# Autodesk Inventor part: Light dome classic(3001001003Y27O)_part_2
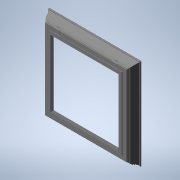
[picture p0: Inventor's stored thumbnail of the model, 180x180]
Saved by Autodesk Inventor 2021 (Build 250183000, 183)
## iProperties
Created: 2026-04
Part Number: Light dome classic(3001001003Y27O)_part_2
Material: Generic
Catalog Web Link: www.3dfindit.com
Description: Light dome classic_part_2-
Vendor: KINGSPAN
Document SubType Name: Modeling
Designer: psAdmin
Manufacturer: KINGSPAN
Mass: 9238.09 g
Surface Area: 18420.5 cm^2
Volume: 9238.09 cm^3
Density: 1 g/cm^3
Appearance: PSOLRGB-255-255-255
Category: PARTsolutions
Company: KINGSPAN
Title: Light dome classic(3001001003Y27O)_part_2
Author: Cadenas PARTsolutions
PSOL_IDENT_0: {$CADENAS_DATA/23d-libs/kingspan_kla/light_dome_classic/parts/part_2.prj},269 {VTYP=3D},{NB=Light do
PSOL_IDENT_1: me classic(3001001003Y27O)_part_2},{LINA=Light dome classic(3001001003Y27O)_part_2},{NN=Light dome c
PSOL_IDENT_2: lassic_part_2},{DATE=20.03.2025 09:30:52},{GEOMDATE=04.07.2024 05:51:00},{VERSION=},{LINEID=10},{WBV
PSOL_IDENT_3: AR=LODLEVEL,L,W,BA,SF,DP,OP,OC},{WBNUMERIC=W}  {NB=Light dome classic(3001001003Y27O)_part_2},{LINA=
PSOL_IDENT_4: Light dome classic(3001001003Y27O)_part_2},{KT=DUMMY},{IDNR=},{PN=Light dome classic},{LODLEVEL=300}
PSOL_IDENT_5: ,{L=100},{W=100},{WX=100,150,200,250,300},{LX=1000},{XWX=1000},{BA=3},{SF=Y},{SFX='Y','Yes','N','No'
PSOL_IDENT_6: },{DRIVE=1},{DPX='1', 'Natural ventilation', '2' , 'NSHEV (natural smoke, heat exhaust ventilation)'
PSOL_IDENT_7: , '3', 'Fixed','4','NSHE'},{DP=2},{OPX='7','24/48 V OPEN/CLOSE including ventilation function'},{OP=
PSOL_IDENT_8: 7},{OCX='O', 'Open', 'C', 'Closed'},{OC=O},{BAXX=56.97},{BAX='3', 'AK50 PVC', '2', 'AK30 PVC' , '7'
PSOL_IDENT_9: , 'AK30 AL/ST', '8', 'AK40 AL/ST', '9'  , 'AK50 AL/ST', '13' , 'AK30 AL/AL', '14' , 'AK40 AL/AL', '
PSOL_IDENT_10: 15' , 'AK50 AL/AL', '16' , 'AK50 ST-TG', '10', 'AK30 ST', '11'  , 'AK40 ST', '12', 'AK50 ST'}
NB: Light dome classic(3001001003Y27O)_part_2
NN: Light dome classic_part_2
NBSYN: $PN.($LODLEVEL.$L.$W.$BA.$SF.$DP.$OP.$OC.)_part_2
LINA: Light dome classic(3001001003Y27O)_part_2
CATALOG: Light + Air
PN: Light dome classic
LODLEVEL: 300
L: 100
W: 100
BA: AK50 PVC
SF: Yes
DP: NSHEV (natural smoke, heat exhaust ventilation)
OP: 24/48 V OPEN/CLOSE including ventilation function
OC: Open
SUPPLIER: KINGSPAN
ARTICLENO: Light dome classic(3001001003Y27O)_part_2
BOMINFO: Light dome classic(3001001003Y27O)_part_2
CREATOR: CADENAS GmbH
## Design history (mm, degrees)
sketch "Sketch_1"
  geometry: L1 (-393, 332)-(-395.2, 332); L2 (-395.2, 332)-(-395.2, 327); L3 (-395.2, 327)-(-424, 327); L4 (-424, 327)-(-424, 316); L5 (-424, 316)-(-467.8, 316); L6 (-472, 311.8)-(-472, 306.773); L7 (-477, 298.113)-(-489.32, 291); L8 (-489.32, 291)-(-500.849, 274.535); L9 (-500.849, 274.535)-(-496.754, 271.668); L10 (-496.754, 271.668)-(-508.226, 255.284); L11 (-508.226, 255.284)-(-504.129, 252.415); L12 (-504.129, 252.415)-(-515.6, 236.032); L13 (-515.6, 236.032)-(-511.507, 233.166); L14 (-511.507, 233.166)-(-521.208, 219.311); L15 (-521.208, 219.311)-(-532.773, 219.311); L16 (-532.773, 219.311)-(-532.773, 204.131); L17 (-532.773, 204.131)-(-525.173, 204.131); L18 (-519.959, 217.26)-(-508.443, 233.706); L19 (-508.443, 233.706)-(-512.536, 236.572); L20 (-512.536, 236.572)-(-501.065, 252.955); L21 (-501.065, 252.955)-(-505.162, 255.824); L22 (-505.162, 255.824)-(-493.69, 272.208); L23 (-493.69, 272.208)-(-497.785, 275.075); L24 (-497.785, 275.075)-(-487.798, 289.339); L25 (-487.798, 289.339)-(-481.456, 293); L26 (-481.456, 293)-(-393, 293); L27 (-393, 293)-(-393, 332); A1 r 4.2 centre (-467.8, 311.8) between (-467.8, 316) and (-472, 311.8); A2 r 10 centre (-482, 306.773) between (-477, 298.113) and (-472, 306.773); A3 r 7.6 centre (-525.173, 211.731) between (-525.173, 204.131) and (-519.959, 217.26)
  constraints: 54 end point, 6 point on circle, 3 centre point
extrude "Extrusion1" join sketch "Sketch_1" stored distance "d0" = 2000; taper "d1" = 0 deg
sketch "Sketch_2"
  geometry: L1 (388.2, 332)-(386, 332); L2 (386, 332)-(386, 293); L3 (386, 293)-(474.456, 293); L4 (474.456, 293)-(480.798, 289.339); L5 (480.798, 289.339)-(490.785, 275.075); L6 (490.785, 275.075)-(486.69, 272.208); L7 (486.69, 272.208)-(498.162, 255.824); L8 (498.162, 255.824)-(494.065, 252.955); L9 (494.065, 252.955)-(505.536, 236.572); L10 (505.536, 236.572)-(501.443, 233.706); L11 (501.443, 233.706)-(512.959, 217.26); L12 (518.173, 204.131)-(525.77, 204.131); L13 (525.77, 204.131)-(525.77, 219.311); L14 (525.77, 219.311)-(514.208, 219.311); L15 (514.208, 219.311)-(504.507, 233.166); L16 (504.507, 233.166)-(508.6, 236.032); L17 (508.6, 236.032)-(497.129, 252.415); L18 (497.129, 252.415)-(501.226, 255.284); L19 (501.226, 255.284)-(489.754, 271.668); L20 (489.754, 271.668)-(493.849, 274.535); L21 (493.849, 274.535)-(482.32, 291); L22 (482.32, 291)-(470, 298.113); L23 (465, 306.773)-(465, 311.8); L24 (460.8, 316)-(417, 316); L25 (417, 316)-(417, 327); L26 (417, 327)-(388.2, 327); L27 (388.2, 327)-(388.2, 332); A1 r 7.6 centre (518.173, 211.731) between (512.959, 217.26) and (518.173, 204.131); A2 r 10 centre (475, 306.773) between (465, 306.773) and (470, 298.113); A3 r 4.2 centre (460.8, 311.8) between (465, 311.8) and (460.8, 316)
  constraints: 54 end point, 6 point on circle, 3 centre point
extrude "Extrusion2" join sketch "Sketch_2" stored distance "d2" = 2000; taper "d3" = 0 deg
sketch "Sketch_3"
  geometry: L1 (534.773, 204.131)-(534.773, 219.311); L2 (534.773, 219.311)-(521.208, 219.311); L3 (521.208, 219.311)-(511.507, 233.166); L4 (511.507, 233.166)-(515.6, 236.032); L5 (515.6, 236.032)-(504.129, 252.415); L6 (504.129, 252.415)-(508.226, 255.284); L7 (508.226, 255.284)-(496.754, 271.668); L8 (496.754, 271.668)-(500.849, 274.535); L9 (500.849, 274.535)-(489.32, 291); L10 (489.32, 291)-(477, 298.113); L11 (472, 306.773)-(472, 311.8); L12 (467.8, 316)-(424, 316); L13 (424, 316)-(424, 327); L14 (424, 327)-(395.2, 327); L15 (395.2, 327)-(395.2, 332); L16 (395.2, 332)-(393, 332); L17 (393, 332)-(393, 293); L18 (393, 293)-(481.456, 293); L19 (481.456, 293)-(487.798, 289.339); L20 (487.798, 289.339)-(497.785, 275.075); L21 (497.785, 275.075)-(493.69, 272.208); L22 (493.69, 272.208)-(505.162, 255.824); L23 (505.162, 255.824)-(501.065, 252.955); L24 (501.065, 252.955)-(512.536, 236.572); L25 (512.536, 236.572)-(508.443, 233.706); L26 (508.443, 233.706)-(519.959, 217.26); L27 (525.173, 204.131)-(534.773, 204.131); A1 r 10 centre (482, 306.773) between (472, 306.773) and (477, 298.113); A2 r 4.2 centre (467.8, 311.8) between (472, 311.8) and (467.8, 316); A3 r 7.6 centre (525.173, 211.731) between (519.959, 217.26) and (525.173, 204.131)
  constraints: 54 end point, 6 point on circle, 3 centre point
extrude "Extrusion3" join sketch "Sketch_3" stored distance "d4" = 2000; taper "d5" = 0 deg
sketch "Sketch_4"
  geometry: L1 (-388.2, 332)-(-388.2, 327); L2 (-388.2, 327)-(-417, 327); L3 (-417, 327)-(-417, 316); L4 (-417, 316)-(-460.8, 316); L5 (-465, 311.8)-(-465, 306.773); L6 (-470, 298.113)-(-482.32, 291); L7 (-482.32, 291)-(-493.849, 274.535); L8 (-493.849, 274.535)-(-489.754, 271.668); L9 (-489.754, 271.668)-(-501.226, 255.284); L10 (-501.226, 255.284)-(-497.129, 252.415); L11 (-497.129, 252.415)-(-508.6, 236.032); L12 (-508.6, 236.032)-(-504.507, 233.166); L13 (-504.507, 233.166)-(-514.208, 219.311); L14 (-514.208, 219.311)-(-525.77, 219.311); L15 (-525.77, 219.311)-(-525.77, 204.131); L16 (-525.77, 204.131)-(-518.173, 204.131); L17 (-512.959, 217.26)-(-501.443, 233.706); L18 (-501.443, 233.706)-(-505.536, 236.572); L19 (-505.536, 236.572)-(-494.065, 252.955); L20 (-494.065, 252.955)-(-498.162, 255.824); L21 (-498.162, 255.824)-(-486.69, 272.208); L22 (-486.69, 272.208)-(-490.785, 275.075); L23 (-490.785, 275.075)-(-480.798, 289.339); L24 (-480.798, 289.339)-(-474.456, 293); L25 (-474.456, 293)-(-386, 293); L26 (-386, 293)-(-386, 332); L27 (-386, 332)-(-388.2, 332); A1 r 4.2 centre (-460.8, 311.8) between (-460.8, 316) and (-465, 311.8); A2 r 10 centre (-475, 306.773) between (-470, 298.113) and (-465, 306.773); A3 r 7.6 centre (-518.173, 211.731) between (-518.173, 204.131) and (-512.959, 217.26)
  constraints: 54 end point, 6 point on circle, 3 centre point
extrude "Extrusion4" join sketch "Sketch_4" stored distance "d6" = 2000; taper "d7" = 0 deg
sketch "Sketch_5"
  geometry: L1 (-393, 357)-(-1093, 357); L2 (-1093, 357)-(-1093, 80.939); L3 (-1093, 80.939)-(-527.437, 180.866); L4 (-527.437, 180.866)-(-532.657, 210.409); L5 (-525.724, 219.311)-(-521.208, 219.311); L6 (-521.208, 219.311)-(-511.507, 233.166); L7 (-511.507, 233.166)-(-515.6, 236.032); L8 (-515.6, 236.032)-(-504.129, 252.415); L9 (-504.129, 252.415)-(-508.226, 255.284); L10 (-508.226, 255.284)-(-496.754, 271.668); L11 (-496.754, 271.668)-(-500.849, 274.535); L12 (-500.849, 274.535)-(-489.32, 291); L13 (-489.32, 291)-(-477, 298.113); L14 (-472, 306.773)-(-472, 311.8); L15 (-467.8, 316)-(-424, 316); L16 (-424, 316)-(-424, 327); L17 (-424, 327)-(-395.2, 327); L18 (-395.2, 327)-(-395.2, 334); L19 (-395.2, 334)-(-393, 334); L20 (-393, 334)-(-393, 357); A1 r 7.6 centre (-525.173, 211.731) between (-525.724, 219.311) and (-532.657, 210.409); A2 r 10 centre (-482, 306.773) between (-477, 298.113) and (-472, 306.773); A3 r 4.2 centre (-467.8, 311.8) between (-467.8, 316) and (-472, 311.8)
  constraints: 40 end point, 6 point on circle, 3 centre point
extrude "Extrusion5" cut sketch "Sketch_5" stored distance "d8" = 2000; taper "d9" = 0 deg
sketch "Sketch_6"
  geometry: L1 (1093, 80.939)-(1093, 357); L2 (1093, 357)-(393, 357); L3 (393, 357)-(393, 334); L4 (393, 334)-(395.2, 334); L5 (395.2, 334)-(395.2, 327); L6 (395.2, 327)-(424, 327); L7 (424, 327)-(424, 316); L8 (424, 316)-(467.8, 316); L9 (472, 311.8)-(472, 306.773); L10 (477, 298.113)-(489.32, 291); L11 (489.32, 291)-(500.849, 274.535); L12 (500.849, 274.535)-(496.754, 271.668); L13 (496.754, 271.668)-(508.226, 255.284); L14 (508.226, 255.284)-(504.129, 252.415); L15 (504.129, 252.415)-(515.6, 236.032); L16 (515.6, 236.032)-(511.507, 233.166); L17 (511.507, 233.166)-(521.208, 219.311); L18 (521.208, 219.311)-(525.724, 219.311); L19 (532.657, 210.409)-(527.437, 180.866); L20 (527.437, 180.866)-(1093, 80.939); A1 r 4.2 centre (467.8, 311.8) between (472, 311.8) and (467.8, 316); A2 r 10 centre (482, 306.773) between (472, 306.773) and (477, 298.113); A3 r 7.6 centre (525.173, 211.731) between (532.657, 210.409) and (525.724, 219.311)
  constraints: 40 end point, 6 point on circle, 3 centre point
extrude "Extrusion6" cut sketch "Sketch_6" stored distance "d10" = 2000; taper "d11" = 0 deg
sketch "Sketch_7"
  geometry: L1 (1086, 357)-(386, 357); L2 (386, 357)-(386, 334); L3 (386, 334)-(388.2, 334); L4 (388.2, 334)-(388.2, 327); L5 (388.2, 327)-(417, 327); L6 (417, 327)-(417, 316); L7 (417, 316)-(460.8, 316); L8 (465, 311.8)-(465, 306.773); L9 (470, 298.113)-(482.32, 291); L10 (482.32, 291)-(493.849, 274.535); L11 (493.849, 274.535)-(489.754, 271.668); L12 (489.754, 271.668)-(501.226, 255.284); L13 (501.226, 255.284)-(497.129, 252.415); L14 (497.129, 252.415)-(508.6, 236.032); L15 (508.6, 236.032)-(504.507, 233.166); L16 (504.507, 233.166)-(514.208, 219.311); L17 (514.208, 219.311)-(518.724, 219.311); L18 (525.657, 210.409)-(516.957, 161.171); L19 (516.957, 161.171)-(1086, 60.629); L20 (1086, 60.629)-(1086, 357); A1 r 4.2 centre (460.8, 311.8) between (465, 311.8) and (460.8, 316); A2 r 10 centre (475, 306.773) between (465, 306.773) and (470, 298.113); A3 r 7.6 centre (518.173, 211.731) between (525.657, 210.409) and (518.724, 219.311)
  constraints: 40 end point, 6 point on circle, 3 centre point
extrude "Extrusion7" cut sketch "Sketch_7" stored distance "d12" = 2000; taper "d13" = 0 deg
sketch "Sketch_8"
  geometry: L1 (-1086, 357)-(-1086, 60.629); L2 (-1086, 60.629)-(-516.957, 161.171); L3 (-516.957, 161.171)-(-525.657, 210.409); L4 (-518.724, 219.311)-(-514.208, 219.311); L5 (-514.208, 219.311)-(-504.507, 233.166); L6 (-504.507, 233.166)-(-508.6, 236.032); L7 (-508.6, 236.032)-(-497.129, 252.415); L8 (-497.129, 252.415)-(-501.226, 255.284); L9 (-501.226, 255.284)-(-489.754, 271.668); L10 (-489.754, 271.668)-(-493.849, 274.535); L11 (-493.849, 274.535)-(-482.32, 291); L12 (-482.32, 291)-(-470, 298.113); L13 (-465, 306.773)-(-465, 311.8); L14 (-460.8, 316)-(-417, 316); L15 (-417, 316)-(-417, 327); L16 (-417, 327)-(-388.2, 327); L17 (-388.2, 327)-(-388.2, 334); L18 (-388.2, 334)-(-386, 334); L19 (-386, 334)-(-386, 357); L20 (-386, 357)-(-1086, 357); A1 r 7.6 centre (-518.173, 211.731) between (-518.724, 219.311) and (-525.657, 210.409); A2 r 10 centre (-475, 306.773) between (-470, 298.113) and (-465, 306.773); A3 r 4.2 centre (-460.8, 311.8) between (-460.8, 316) and (-465, 311.8)
  constraints: 40 end point, 6 point on circle, 3 centre point
extrude "Extrusion8" cut sketch "Sketch_8" stored distance "d14" = 2000; taper "d15" = 0 deg
sketch "Sketch_13"
  geometry: L1 (-319.461, 417.103)-(-318, 417); L2 (-318, 417)-(-316, 417); L3 (-316, 417)-(-316, 464.531); L4 (-316, 464.531)-(-303.205, 474.473); L5 (-308.009, 473.974)-(-307.436, 475.954); L6 (-304.441, 476.046)-(-318, 465.51); L7 (-318, 465.51)-(-318, 421); L8 (-318, 421)-(-319.461, 417.103); A1 r 4.5 centre (-306, 478) between (-303.205, 474.473) and (-308.009, 473.974); A2 r 2.5 centre (-306, 478) between (-304.441, 476.046) and (-307.436, 475.954)
  constraints: 16 end point, 4 point on circle, 2 centre point
extrude "Extrusion9" join sketch "Sketch_13" distance "d16" = 70; taper "d17" = 0 deg
sketch "Sketch_14"
  geometry: L1 (-319.461, 417.103)-(-318, 417); L2 (-318, 417)-(-316, 417); L3 (-316, 417)-(-316, 464.531); L4 (-316, 464.531)-(-303.205, 474.473); L5 (-308.009, 473.974)-(-307.436, 475.954); L6 (-304.441, 476.046)-(-318, 465.51); L7 (-318, 465.51)-(-318, 421); L8 (-318, 421)-(-319.461, 417.103); A1 r 4.5 centre (-306, 478) between (-303.205, 474.473) and (-308.009, 473.974); A2 r 2.5 centre (-306, 478) between (-304.441, 476.046) and (-307.436, 475.954)
  constraints: 16 end point, 4 point on circle, 2 centre point
extrude "Extrusion10" join sketch "Sketch_14" distance "d18" = 70; taper "d19" = 0 deg
sketch "Sketch_15"
  geometry: L1 (299, 492.5)-(299, 471.42); L2 (299, 471.42)-(317.5, 471.42); L3 (317.5, 471.42)-(317.5, 482.5); L4 (317.5, 482.5)-(350.5, 482.5); L5 (350.5, 482.5)-(350.5, 471.42); L6 (350.5, 471.42)-(369, 471.42); L7 (369, 471.42)-(369, 492.5); L8 (369, 492.5)-(299, 492.5)
  constraints: 16 end point
extrude "Extrusion11" cut sketch "Sketch_15" distance "d20" = 20; taper "d21" = 0 deg
sketch "Sketch_16"
  geometry: L1 (-369, 471.42)-(-350.5, 471.42); L2 (-350.5, 471.42)-(-350.5, 482.5); L3 (-350.5, 482.5)-(-317.5, 482.5); L4 (-317.5, 482.5)-(-317.5, 471.42); L5 (-317.5, 471.42)-(-299, 471.42); L6 (-299, 471.42)-(-299, 492.5); L7 (-299, 492.5)-(-369, 492.5); L8 (-369, 492.5)-(-369, 471.42)
  constraints: 16 end point
extrude "Extrusion12" cut sketch "Sketch_16" distance "d22" = 20; taper "d23" = 0 deg
sketch "Sketch_21"
  geometry: L1 (-521.208, 224.311)-(-555.173, 224.311); L2 (-555.173, 224.311)-(-555.173, 189.311); L3 (-555.173, 189.311)-(-525.173, 189.311); L4 (-525.173, 189.311)-(-525.173, 204.131); L5 (-525.724, 219.311)-(-521.208, 219.311); L6 (-521.208, 219.311)-(-521.208, 224.311); A1 r 7.6 centre (-525.173, 211.731) between (-525.724, 219.311) and (-525.173, 204.131)
  constraints: 12 end point, 2 point on circle, 1 centre point
extrude "Extrusion13" cut sketch "Sketch_21" stored distance "d24" = 2000; taper "d25" = 0 deg
sketch "Sketch_22"
  geometry: L1 (555.173, 224.311)-(521.208, 224.311); L2 (521.208, 224.311)-(521.208, 219.311); L3 (521.208, 219.311)-(525.724, 219.311); L4 (525.173, 204.131)-(525.173, 189.311); L5 (525.173, 189.311)-(555.173, 189.311); L6 (555.173, 189.311)-(555.173, 224.311); A1 r 7.6 centre (525.173, 211.731) between (525.173, 204.131) and (525.724, 219.311)
  constraints: 12 end point, 2 point on circle, 1 centre point
extrude "Extrusion14" cut sketch "Sketch_22" stored distance "d26" = 2000; taper "d27" = 0 deg
sketch "Sketch_23"
  geometry: L1 (535.77, 224.311)-(514.208, 224.311); L2 (514.208, 224.311)-(514.208, 219.311); L3 (514.208, 219.311)-(518.724, 219.311); L4 (518.173, 204.131)-(518.173, 189.311); L5 (518.173, 189.311)-(535.77, 189.311); L6 (535.77, 189.311)-(535.77, 224.311); A1 r 7.6 centre (518.173, 211.731) between (518.173, 204.131) and (518.724, 219.311)
  constraints: 12 end point, 2 point on circle, 1 centre point
extrude "Extrusion15" cut sketch "Sketch_23" stored distance "d28" = 2000; taper "d29" = 0 deg
sketch "Sketch_24"
  geometry: L1 (-535.77, 224.311)-(-535.77, 189.311); L2 (-535.77, 189.311)-(-518.173, 189.311); L3 (-518.173, 189.311)-(-518.173, 204.131); L4 (-518.724, 219.311)-(-514.208, 219.311); L5 (-514.208, 219.311)-(-514.208, 224.311); L6 (-514.208, 224.311)-(-535.77, 224.311); A1 r 7.6 centre (-518.173, 211.731) between (-518.724, 219.311) and (-518.173, 204.131)
  constraints: 12 end point, 2 point on circle, 1 centre point
extrude "Extrusion16" cut sketch "Sketch_24" stored distance "d30" = 2000; taper "d31" = 0 deg
node "IP_2_XY"
node "IP_2_YZ"
node "IP_2_ZX"
node "IP_2_X"
node "IP_2_Y"
node "IP_2_Z"
node "IP_2_Center"
node "IP_for_part_3_XY"
node "IP_for_part_3_YZ"
node "IP_for_part_3_ZX"
node "IP_for_part_3_X"
node "IP_for_part_3_Y"
node "IP_for_part_3_Z"
node "IP_for_part_3_Center"
node "IP_for_part_8_1_XY"
node "IP_for_part_8_1_YZ"
node "IP_for_part_8_1_ZX"
node "IP_for_part_8_1_X"
node "IP_for_part_8_1_Y"
node "IP_for_part_8_1_Z"
node "IP_for_part_8_1_Center"
node "IP_for_part_8_2_XY"
node "IP_for_part_8_2_YZ"
node "IP_for_part_8_2_ZX"
node "IP_for_part_8_2_X"
node "IP_for_part_8_2_Y"
node "IP_for_part_8_2_Z"
node "IP_for_part_8_2_Center"
node "IP_for_part_8_3_XY"
node "IP_for_part_8_3_YZ"
node "IP_for_part_8_3_ZX"
node "IP_for_part_8_3_X"
node "IP_for_part_8_3_Y"
node "IP_for_part_8_3_Z"
node "IP_for_part_8_3_Center"
node "IP_for_part_8_4_XY"
node "IP_for_part_8_4_YZ"
node "IP_for_part_8_4_ZX"
node "IP_for_part_8_4_X"
node "IP_for_part_8_4_Y"
node "IP_for_part_8_4_Z"
node "IP_for_part_8_4_Center"
node "IP_for_part_8_5_XY"
node "IP_for_part_8_5_YZ"
node "IP_for_part_8_5_ZX"
node "IP_for_part_8_5_X"
node "IP_for_part_8_5_Y"
node "IP_for_part_8_5_Z"
node "IP_for_part_8_5_Center"
node "IP_for_part_9_XY"
node "IP_for_part_9_YZ"
node "IP_for_part_9_ZX"
node "IP_for_part_9_X"
node "IP_for_part_9_Y"
node "IP_for_part_9_Z"
node "IP_for_part_9_Center"
body "Solid1"
other parameters: "d32" = 0
